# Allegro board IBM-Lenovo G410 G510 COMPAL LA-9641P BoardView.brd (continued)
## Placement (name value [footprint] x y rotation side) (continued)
PC635  -  [C_0402]  167.15 128.39 0 top
PC636  -  [C_0402]  176.52 126.08 270 top
PC637  -  [C_0402]  199.32 11.66 0 top
PC638  -  [C_0402]  170.43 131.14 270 top
PC701  -  [C_0402]  99.53 33.63 180 top
PC702  -  [C_0402]  101.62 28.75 0 top
PC703  -  [C_0402]  104.3 28.78 180 top
PC704  -  [C_0402]  105.73 27.89 90 top
PC705  -  [C_0402]  107.8 29.68 180 top
PC706  -  [C_0402]  107.8 30.83 180 top
PC707  -  [C_0603]  102.15 37.23 270 top
PC708  -  [C_0603]  104.83 35.76 90 top
PC709  -  [C_0603]  116.18 45.19 0 top
PC711  -  [C_0402]  118.59 31.35 0 top
PC712  -  [C_0805]  118.45 29.96 0 top
PC713  -  [C_0805]  118.1 33.61 0 top
PC714  -  [C_MP6VLPS220MC4R2]  113.03 49.15 0 bottom
PC715  -  [C_0402]  118.59 32.3 0 top
PC801  -  [C_0402]  178.47 142.44 90 bottom
PC802  -  [C_0402]  179.36 142.44 90 bottom
PC803  -  [C_0805]  173.42 141.21 180 top
PC804  -  [C_0805]  173.39 139.43 180 top
PC805  -  [C_0402]  186.87 136.34 270 bottom
PC806  -  [C_0603]  180.67 137.09 0 top
PC807  -  [C_D2]  160.89 144.4 90 top
PC808  -  [C_D2]  165.84 144.45 90 top
PC809  -  [C_D2]  160.78 140.14 270 top
PC810  -  [C_D2]  165.72 140 270 top
PC811  -  [C_0402]  169.57 134.43 0 top
PC812  -  [C_0603]  184.25 138.68 0 bottom
PC824  -  [C_0402]  141.99 142.15 270 top
PC825  -  [C_0402]  133.84 138.14 270 top
PC826  -  [C_0402]  132.96 147.23 180 top
PC827  -  [C_0402]  139.89 140.14 270 top
PC828  -  [C_0402]  133.84 144.69 90 top
PC829  -  [C_0402]  137.87 142.62 270 top
PC830  -  [C_0402]  135.81 138.11 270 top
PC831  -  [C_0402]  136.86 146.97 270 top
PC832  -  [C_0402]  137.85 144.69 90 top
PC833  -  [C_0402]  141.87 143.89 90 top
PC834  -  [C_0402]  137.89 140.14 270 top
PC835  -  [C_0402]  135.78 140.14 270 top
PC836  -  [C_0402]  133.84 142.62 270 top
PC837  -  [C_0402]  131.77 144.73 90 top
PC838  -  [C_0402]  131.8 140.14 270 top
PC839  -  [C_0402]  133.84 140.14 270 top
PC840  -  [C_0603]  152.64 138.1 270 top
PC841  -  [C_0603]  153.91 138.08 270 top
PC842  -  [C_0603]  156.45 138.13 270 top
PC843  -  [C_0603]  155.18 138.12 270 top
PC844  -  [C_0603]  143.1 142.34 270 top
PC845  -  [C_0603]  154.62 138.17 270 bottom
PC846  -  [C_0603]  155.87 138.19 270 bottom
PC847  -  [C_0402]  192.46 142.35 180 bottom
PC848  -  [C_0402]  192.67 138.93 0 top
PC849  -  [C_0402]  187.96 144.17 90 bottom
PC850  -  [C_0402]  191.55 140.51 0 bottom
PC851  -  [C_0402]  135.78 142.62 270 top
PC852  -  [C_0402]  138.87 147.04 270 top
PC853  -  [C_0402]  139.86 144.19 90 top
PC854  -  [C_0402]  137.89 138.08 270 top
PC855  -  [C_0402]  139.89 142.62 270 top
PC856  -  [C_0402]  131.8 142.62 270 top
PC857  -  [C_0402]  135.78 144.75 90 top
PC858  -  [C_0603]  182.36 142.78 270 top
PC859  -  [C_0402]  189.9 139.34 180 bottom
PC860  -  [C_0603]  183.3 145.32 270 top
PC861  -  [C_0603]  182.02 145.32 270 top
PC862  -  [C_0402]  189.22 140.22 90 bottom
PC863  -  [C_0402]  189.15 143.29 180 bottom
PC864  -  [C_0402]  185.87 143.96 270 bottom
PC865  -  [C_0402]  171.36 149.27 0 top
PC866  -  [C_0402]  184.95 141.26 270 bottom
PC871  -  [C_0402]  191.77 138.95 90 top
PC872  -  [C_0603]  184.25 137.42 0 bottom
PC873  -  [C_0402]  191.73 137.92 90 bottom
PC874  -  [C_0402]  190.09 144.04 180 top
PC875  -  [C_0402]  191.55 141.4 0 bottom
PC876  -  [C_0603]  187.26 141.21 270 bottom
PC877  -  [C_0603]  186.03 141.2 270 bottom
PC878  -  [C_0402]  176.53 142.45 90 bottom
PC879  -  [C_0402]  177.5 142.43 90 bottom
PC880  -  [C_0805]  178.49 145.24 180 top
PC881  -  [C_0805]  178.49 147.04 180 top
PC901  -  [C_0402]  20.41 117.39 270 top
PC902  -  [C_0402]  17.65 123.01 270 top
PC903  -  [C_0402]  17.67 123.03 0 bottom
PC904  -  [C_0402]  18.59 121.19 270 top
PC905  -  [C_0402]  18.56 119.4 180 bottom
PC906  -  [C_0402]  17.67 121.23 0 bottom
PC907  -  [C_0603]  21.82 122.04 180 top
PC908  -  [C_0402]  18.56 118.49 180 bottom
PC909  -  [C_0402]  21.28 123.13 90 top
PC910  -  [C_0402]  21.34 117.38 270 top
PC911  -  [C_0402]  23.29 118.29 90 top
PC912  -  [C_0402]  25.17 123.13 90 top
PC913  -  [C_0402]  26.48 117.96 90 top
PC914  -  [C_0603]  26.3 119.98 90 top
PC915  -  [C_0402]  29.19 123.42 270 bottom
PC916  -  [C_0402]  20.42 115.48 270 top
PC917  -  [C_0402]  23.22 115.46 270 top
PC918  -  [C_0402]  26.7 115.43 270 top
PC919  -  [C_0603]  27.48 91.24 180 top
PC920  -  [C_0805]  32.41 126.21 180 top
PC922  -  [C_0603]  29.33 116.76 180 bottom
PC923  -  [C_0402]  31.67 94.14 0 top
PC925  -  [C_0805]  32.47 128.02 180 top
PC930  -  [C_0603]  37.24 96.56 180 bottom
PC932  -  [C_0805]  28.41 97.35 0 top
PC933  -  [C_0805]  28.38 99.1 0 top
PC938  -  [C_0805]  26.14 96.91 180 top
PC939  -  [C_0805]  26.13 98.74 180 top
PC940  -  [C_0603]  17.56 96.63 0 top
PC942  -  [C_0402]  25.5 95.49 180 top
PC943  -  [C_0402]  29.31 128.56 270 top
PC944  -  [C_0402]  28.42 128.55 270 top
PC945  -  [C_0402]  25.51 94.59 180 top
PC946  -  [C_0805]  67.54 94.32 90 bottom
PC947  -  [C_0805]  57.69 125.93 90 bottom
PC949  -  [C_0805]  77.23 99.85 270 bottom
PC950  -  [C_0805]  57.69 125.94 90 top
PC951  -  [C_D2]  53.58 123.02 90 top
PC952  -  [C_0805]  70.07 94.32 90 bottom
PC953  -  [C_0805]  59.12 117.23 180 top
PC954  -  [C_D2]  66.36 102.08 0 top
PC955  -  [C_0805]  72.56 99.86 270 bottom
PC956  -  [C_0805]  61.18 125.95 90 bottom
PC957  -  [C_D2]  49.66 122.99 90 bottom
PC958  -  [C_0805]  74.99 99.86 270 bottom
PC959  -  [C_0805]  74.99 98.15 270 top
PC960  -  [C_D2]  54.42 123.02 90 bottom
PC961  -  [C_0805]  72.51 94.31 90 bottom
PC962  -  [C_0805]  65.32 98.15 270 top
PC963  -  [C_0805]  77.24 94.31 90 bottom
PC964  -  [C_0805]  65.29 94.32 90 bottom
PC965  -  [C_0805]  65.32 99.85 270 bottom
PC966  -  [C_0805]  61 94.32 90 bottom
PC967  -  [C_0805]  63.17 99.89 270 bottom
PC968  -  [C_0805]  68.93 119.91 0 bottom
PC969  -  [C_0805]  61.17 125.97 90 top
PC970  -  [C_0805]  58.7 99.87 270 bottom
PC971  -  [C_0805]  59.43 125.94 90 bottom
PC972  -  [C_0805]  70.1 98.23 270 top
PC973  -  [C_0805]  60.91 99.89 270 bottom
PC974  -  [C_0805]  59.43 125.96 90 top
PC975  -  [C_0805]  58.87 94.32 90 bottom
PC976  -  [C_0805]  67.6 99.87 270 bottom
PC977  -  [C_0805]  60.92 98.18 270 top
PC978  -  [C_0805]  72.58 98.16 270 top
PC979  -  [C_0805]  70.1 99.94 270 bottom
PC980  -  [C_0805]  75.07 94.31 90 bottom
PC981  -  [C_0805]  63.17 98.19 270 top
PC982  -  [C_0805]  58.72 98.16 270 top
PC983  -  [C_0805]  63.14 94.31 90 bottom
PC984  -  [C_0805]  76.8 98.15 270 top
PC985  -  [C_MVY25VC220MH10E0-J]  79.5 135.24 45 bottom
PC986  -  [C_EEEFZ1E101P]  25.8 94.9 180 bottom
PC987  -  [C_0402]  22.19 124.04 270 top
PC988  -  [C_0402]  28.56 96 0 top
PC989  -  [C_0402]  28.14 113.47 0 top
PD101  -  [RB715F_SOT323-3]  197.71 29.3 180 top
PD104  -  [1N4148WS-7-F_SOD323-2]  186.49 121.54 180 top
PD105  -  [1N4148WS-7-F_SOD323-2]  181.7 112.42 0 top
PD201  -  [1N4148WS-7-F_SOD323-2]  183.5 65.69 90 top
PD203  -  [1N4148WS-7-F_SOD323-2]  174.49 63.61 90 top
PD301  -  [RB751V-40_SOD323-2]  183.43 167.57 90 top
PD302  -  [1SS355_SOD323-2]  163.08 173.57 180 top
PD303  -  [1SS355_SOD323-2]  165.04 173.64 270 top
PD601  -  [RB751V-40_SOD323-2]  114.35 172.87 270 bottom
PF101  -  [F_451012MRL]  193.61 150.05 270 bottom
PF201  -  [F_451012MRL]  177.15 172.3 0 bottom
PH201  -  [R_0402]  67.1 96.4 0 top
PH802  -  [R_0402]  165.23 140.84 180 bottom
PH901  -  [R_0402]  42.27 129.47 270 bottom
PH902  -  [R_0402]  33.52 115.98 180 top
PJ1  -  [JUMP_43X79]  147.85 93.25 0 top
PJ2  -  [JUMP_43X39]  135.45 63.23 0 top
PJ3  -  [JUMP_43X39]  135.45 60.84 0 top
PJ202  -  [JUMP_43X39]  191.54 61.09 270 top
PJ401  -  [JUMP_43X118]  87.61 13.02 90 top
PJ402  -  [JUMP_43X118]  121.36 11.17 0 bottom
PJ503  -  [JUMP_43X39]  36.9 9.61 0 top
PJ504  -  [JUMP_43X118]  61.6 23.16 270 top
PJ505  -  [JUMP_43X118]  56.24 23.17 270 top
PJ506  -  [JUMP_43X79]  32.3 14.52 0 top
PJ602  -  [JUMP_43X118]  196.55 24 0 top
PJ603  -  [JUMP_43X118]  114.84 164.67 90 bottom
PJ605  -  [JUMP_43X79]  110.56 171.25 0 top
PJ606  -  [JUMP_43X118]  156.87 127.47 90 top
PJ701  -  [JUMP_43X118]  112.44 55.51 270 bottom
PL101  -  [L_1812-1806]  189.89 148.08 180 bottom
PL102  -  [L_1812-1806]  191.88 150.59 180 top
PL201  -  [CHENG_SMB3025500YA_2P]  181.8 168.51 180 bottom
PL301  -  [CYNTE_PCMB063T-100MS_2P]  179.94 158.67 90 bottom
PL302  -  [KARSO_KJ1040-3R3M_2P]  170.67 159.62 90 bottom
PL401  -  [TAI-T_HCB2012KF-121T50_2P]  61.45 3.05 90 bottom
PL402  -  [TAI-T_VMPI0703AR-100M-Z01_2P]  71 8.58 0 top
PL403  -  [TAI-T_HCB2012KF-121T50_2P]  92.56 4.2 0 bottom
PL404  -  [TAI-T_VMPI0703AR-100M-Z01_2P]  107.66 9.55 0 bottom
PL501  -  [CYNTE_PCMB104T-1R0MH_2P]  51.15 7.08 180 top
PL502  -  [TAI-T_HCB2012KF-121T50_2P]  56.41 2.29 0 top
PL601  -  [CYNTE_PCMB063T-1R0MS_2P]  204.71 10.06 90 top
PL603  -  [TAI-T_HCB2012KF-121T50_2P]  190.89 6.84 0 bottom
PL604  -  [CYNTE_PHT32251B-1R0MS_2P]  113.53 167.24 0 top
PL605  -  [CYNTE_PCMB063T-1R0MS_2P]  167.07 128.21 180 bottom
PL606  -  [TAI-T_HCB2012KF-121T50_2P]  175.5 130.48 270 top
PL701  -  [CYNTE_PCMB063T-1R0MS_2P]  111.51 37.12 90 bottom
PL702  -  [TAI-T_HCB2012KF-121T50_2P]  113.64 28.71 180 top
PL801  -  [L_1812-1806]  176.85 142.41 270 top
PL802  -  [CYNTE_PDME064T-R36MS1R405_4P]  168.75 135.51 180 bottom
PL803  -  [CYNTE_PDME064T-R36MS1R405_4P]  168.89 147.88 180 bottom
PL901  -  [L_1812-1806]  76.81 135.85 225 top
PL902  -  [TAI-T_VMPI1004AR-R36M-Z03_4P]  31.52 121.71 0 bottom
PL903  -  [TAI-T_VMPI1004AR-R36M-Z03_4P]  38.34 101.36 90 bottom
PL904  -  [TAI-T_VMPI1004AR-R36M-Z03_4P]  17.75 108.06 0 bottom
PQ101  -  [2N7002DW-7-F_SOT363-6]  183.06 115.67 0 top
PQ102  -  [2N7002DW-7-F_SOT363-6]  196.08 79.66 90 top
PQ201  -  [SSM3K7002FU_SC70-3]  178.38 58.85 270 top
PQ202  -  [2N7002DW-7-F_SOT363-6]  181.84 67.06 180 top
PQ205  -  [2N7002W-T-R7_SOT323-3]  183.41 69.83 0 top
PQ206  -  [2N7002W-T-R7_SOT323-3]  184.43 76.79 0 top
PQ207  -  [2N7002W-T-R7_SOT323-3]  190.8 76.88 0 top
PQ208  -  [2N7002W-T-R7_SOT323-3]  187.81 76.82 0 top
PQ209  -  [2N7002W-T-R7_SOT323-3]  178.33 66.75 180 top
PQ301  -  [AO4407A_SO8]  190.29 160.3 180 top
PQ302  -  [AO4407A_SO8]  186.1 160.09 0 bottom
PQ303  -  [DTC115EUA_SC70-3]  183.74 154.82 180 top
PQ304  -  [DTA144EUA_SC70-3]  182.84 153.55 180 bottom
PQ305  -  [DTC115EUA_SC70-3]  179.99 153.52 180 bottom
PQ306  -  [2N7002KW_SOT323-3]  180.82 149.81 270 bottom
PQ307  -  [2N7002DW-7-F_SOT363-6]  183.08 149.85 0 top
PQ308  -  [2N7002W-T-R7_SOT323-3]  194.44 168.1 270 top
PQ309  -  [AO4466L_SO8]  171.97 154.39 0 top
PQ310  -  [AO4466L_SO8]  170.02 161.88 180 top
PQ311  -  [DTC115EUA_SC70-3]  162.42 170.13 0 top
PQ312  -  [AO4407A_SO8]  175.82 162.14 0 top
PQ313  -  [2N7002W-T-R7_SOT323-3]  162.86 165.85 0 bottom
PQ314  -  [2N7002W-T-R7_SOT323-3]  177.21 154.87 0 bottom
PQ501  -  [TPCA8065-H_PPAK56-8-5]  49.13 3.16 90 bottom
PQ502  -  [TPCA8059-H_PPAK56-8-5]  37.77 3.13 90 bottom
PQ701  -  [AO4466L_SO8]  109.67 36.85 270 top
PQ702  -  [AO4466L_SO8]  117.4 38.95 90 top
PQ801  -  [CSD87351Q5D_SON8-7]  177.27 140.13 270 bottom
PQ802  -  [CSD87351Q5D_SON8-7]  177.4 148.26 270 bottom
PQ901  -  [MDU1516URH_POWERDFN56-8-5]  38.61 126.46 270 top
PQ902  -  [MDU1511RH_POWERDFN56-8-5]  30.73 124.33 270 top
PQ903  -  [MDU1516URH_POWERDFN56-8-5]  37.58 101.01 90 top
PQ904  -  [MDU1511RH_POWERDFN56-8-5]  37.07 98.85 270 top
PQ905  -  [MDU1516URH_POWERDFN56-8-5]  30.2 106.14 180 top
PQ906  -  [MDU1511RH_POWERDFN56-8-5]  20.26 100.81 0 top
PR101  -  [R_0603]  195.57 27.29 90 top
PR102  -  [R_0603]  199.78 28.42 270 top
PR103  -  [R_0402]  193.08 80.47 270 top
PR104  -  [R_0402]  182.65 113.77 90 top
PR105  -  [R_0402]  187.18 120.16 180 top
PR106  -  [R_0402]  184.55 113.77 90 top
PR107  -  [R_0402]  187.18 119.24 180 bottom
PR108  -  [R_0402]  189.72 120.81 90 top
PR109  -  [R_0402]  190.59 119.94 180 top
PR110  -  [R_0402]  195.23 82.98 0 top
PR111  -  [R_0402]  196.12 82.03 180 top
PR201  -  [R_0402]  183.08 173.66 0 top
PR202  -  [R_0402]  185.32 62.89 270 top
PR203  -  [R_0402]  190.91 72.88 0 top
PR204  -  [R_0402]  183.09 172.67 0 top
PR205  -  [R_0402]  181.19 62.86 90 top
PR206  -  [R_0402]  185.16 172.07 270 bottom
PR207  -  [R_0402]  184.22 172.05 270 bottom
PR208  -  [R_0402]  175.89 64.53 270 top
PR209  -  [R_0402]  186.11 172.07 0 bottom
PR210  -  [R_0402]  184.39 62.89 270 top
PR211  -  [R_0402]  180.53 68.11 0 top
PR212  -  [R_0402]  187.84 73 90 top
PR213  -  [R_0402]  187.33 62.9 180 top
PR214  -  [R_0402]  182.19 69.02 180 top
PR215  -  [R_0402]  179.15 60.59 180 top
PR216  -  [R_0402]  180.07 61.43 270 top
PR217  -  [R_0402]  191.8 70.89 180 top
PR220  -  [R_0402]  181.44 71.77 270 top
PR225  -  [R_0402]  187.03 80.2 90 top
PR226  -  [R_0402]  182.07 59.86 0 top
PR227  -  [R_0402]  184.51 81.11 270 top
PR228  -  [R_0402]  182.09 61.24 0 top
PR229  -  [R_0402]  189.28 80.2 90 top
PR230  -  [R_0402]  186 80.2 90 top
PR232  -  [R_0402]  192.07 80.2 90 top
PR233  -  [R_0402]  183.48 80.2 90 top
PR301  -  [R_1206_4P-D]  184.42 159.48 180 top
PR302  -  [R_0402]  183.45 152.29 180 bottom
PR303  -  [R_0402]  181.58 153.05 270 bottom
PR304  -  [R_0402]  185.68 152.64 180 bottom
PR305  -  [R_0402]  185.31 148.81 180 top
PR306  -  [R_0402]  182.34 150.48 270 bottom
PR307  -  [R_0402]  194.94 165.33 90 bottom
PR308  -  [R_0402]  194.02 166.26 270 top
PR309  -  [R_0402]  192.2 165.35 0 top
PR310  -  [R_0402]  194.94 165.33 90 top
PR311  -  [R_0402]  178.19 156.17 180 bottom
PR312  -  [R_0402]  196.78 166.24 270 top
PR314  -  [R_0402]  195.86 166.24 270 top
PR315  -  [R_0402]  192.17 168.09 90 top
PR316  -  [R_0402]  192.17 169.91 0 top
PR317  -  [R_0402]  187.98 170.48 90 top
PR318  -  [R_0402]  187.09 170.48 90 top
PR319  -  [R_1206]  184.47 164.59 270 bottom
PR320  -  [R_0603]  182.74 165.75 270 top
PR321  -  [R_0402]  161.96 168.79 0 top
PR322  -  [R_0402]  162.88 167.86 180 top
PR323  -  [R_1206]  171.65 154.58 180 bottom
PR324  -  [R_1206_4P-D]  170.15 165.72 90 top
PR325  -  [R_0402]  162.88 166.93 180 top
PR326  -  [R0603_0OHM]  183.97 165.97 270 top
PR402  -  [R_0402]  110.06 3.24 0 top
PR403  -  [R_0402]  110.98 4.26 90 top
PR404  -  [R_1206]  72.66 13.05 180 top
PR406  -  [R_1206]  104.41 5.89 180 top
PR407  -  [R_0402]  104.55 9.91 90 top
PR408  -  [R_0402]  103.58 9.92 90 top
PR409  -  [R_0402]  103.58 9.04 0 top
PR410  -  [R_0402]  68.18 3.67 90 bottom
PR411  -  [R_0402]  67.36 7.5 270 bottom
PR412  -  [R_0402]  101.79 9.23 90 top
PR413  -  [R_0402]  102.66 9.23 90 top
PR414  -  [R_0402]  65.58 7.46 270 bottom
PR415  -  [R_0402]  68.24 7.5 270 bottom
PR421  -  [R0603_0OHM]  65.18 4.3 0 top
PR422  -  [R0603_0OHM]  97.62 6.77 90 top
PR501  -  [R_0603]  36.66 7.85 0 top
PR502  -  [R_0402]  28.32 9.81 270 top
PR505  -  [R_0402]  28.35 7.07 90 top
PR506  -  [R_0402]  30.49 12.06 90 top
PR507  -  [R_0402]  31.39 11.21 180 top
PR509  -  [R_0402]  28.39 5.69 0 top
PR511  -  [R_0402]  29.31 4.56 180 top
PR514  -  [R_0603]  31.85 4.37 180 top
PR515  -  [R_1206]  45.08 7.03 270 bottom
PR601  -  [R_0402]  199.59 14.17 270 top
PR602  -  [R_0402]  198.7 13.24 90 bottom
PR603  -  [R_1206]  201.04 9.63 0 bottom
PR604  -  [R_0402]  198.66 14.16 270 top
PR605  -  [R_0402]  197.74 13.26 90 top
PR607  -  [R_0402]  196.75 14.14 0 bottom
PR608  -  [R_0402]  197.67 15.05 180 bottom
PR609  -  [R_0402]  173.11 131.5 90 top
PR610  -  [R_1206]  168.82 124.51 0 bottom
PR611  -  [R_0402]  167.15 129.35 0 top
PR612  -  [R_0402]  170.25 131.99 0 top
PR613  -  [R_0402]  199.6 14.16 270 bottom
PR614  -  [R_1206]  111.14 168.5 270 top
PR615  -  [R_0402]  168.68 130.22 90 top
PR616  -  [R_0402]  169.55 131.14 270 top
PR618  -  [R_0402]  172.17 132.41 270 top
PR623  -  [R_0402]  114.49 171.11 0 top
PR624  -  [R_0402]  114.77 174.8 270 top
PR625  -  [R_0402]  114.74 172 90 top
PR626  -  [R_0402]  115.68 171.99 90 top
PR701  -  [R_0402]  98.61 31.71 0 top
PR702  -  [R_0402]  98.68 29.89 90 top
PR704  -  [R_0402]  102.53 27.83 180 top
PR705  -  [R_0402]  104.31 27.83 180 top
PR706  -  [R_0402]  98.61 32.68 0 top
PR707  -  [R_0402]  107.8 27.68 180 top
PR709  -  [R_0402]  106.89 28.76 0 top
PR711  -  [R_0402]  106.41 32.79 0 top
PR712  -  [R_0402]  99.66 30.83 270 top
PR713  -  [R_0603]  100.92 35.84 90 top
PR714  -  [R_1206]  112.26 44.87 0 top
PR801  -  [R_0402]  186.45 134.19 270 bottom
PR802  -  [R_0402]  187.79 133.7 270 bottom
PR803  -  [R_0402]  185.56 134.19 270 bottom
PR804  -  [R_0402]  183.9 134.19 270 bottom
PR805  -  [R_0402]  183 134.19 270 bottom
PR806  -  [R_0402]  181.57 134.18 270 bottom
PR807  -  [R_0402]  187.77 133.67 270 top
PR808  -  [R_0402]  186.46 133.65 270 top
PR809  -  [R_0402]  185.57 133.66 270 top
PR810  -  [R_0402]  183.9 134.19 270 top
PR811  -  [R_0402]  183 134.19 270 top
PR812  -  [R_0402]  181.57 134.2 270 top
PR813  -  [R_0402]  188.68 132.77 90 top
PR814  -  [R_0402]  185.96 135.43 90 bottom
PR816  -  [R_0402]  190.65 133.73 180 top
PR817  -  [R_0603]  180.67 135.87 0 top
PR818  -  [R_0402]  190.82 134.8 180 bottom
PR819  -  [R_0402]  187.8 136.33 270 bottom
PR820  -  [R_0402]  188.73 132.8 90 bottom
PR826  -  [R_1206]  169.53 138.35 270 top
PR827  -  [R_0402]  182.52 142.6 0 bottom
PR828  -  [R_0402]  182.51 143.53 0 bottom
PR829  -  [R_0402]  182.54 144.45 0 bottom
PR830  -  [R_0402]  191.54 133.74 90 top
PR831  -  [R_0402]  190.82 133 90 bottom
PR832  -  [R_0402]  189.88 133 90 bottom
PR833  -  [R_0402]  192.49 136.68 180 top
PR834  -  [R_0402]  192.51 137.58 180 top
PR835  -  [R_0402]  188.96 136.69 0 bottom
PR836  -  [R_0402]  189.96 135.8 180 bottom
PR840  -  [R_0402]  189.88 137.57 180 bottom
PR841  -  [R_0402]  192.65 137.91 90 bottom
PR842  -  [R_0402]  190.06 143.3 0 bottom
PR843  -  [R_0402]  190.09 143.14 180 top
PR844  -  [R_0402]  185.86 143.18 90 top
PR845  -  [R_0402]  181.4 140.65 180 bottom
PR846  -  [R_0402]  193.58 139.85 180 top
PR847  -  [R_0402]  187.05 145.08 270 bottom
PR848  -  [R_0402]  180.48 139.74 0 bottom
PR849  -  [R_0402]  189.87 138.46 180 bottom
PR850  -  [R_0402]  190.62 145.08 270 bottom
PR851  -  [R_0402]  187.36 143.3 90 top
PR852  -  [R_0603]  183.55 142.77 0 top
PR853  -  [R_0402]  183.43 141.65 180 bottom
PR854  -  [R_0402]  189.34 145.08 270 bottom
PR855  -  [R_1206]  169.78 146.27 90 top
PR856  -  [R_0402]  182.52 146.85 0 bottom
PR857  -  [R_0402]  182.5 147.77 0 bottom
PR858  -  [R_0402]  182.53 145.38 0 bottom
PR859  -  [R_0402]  184.42 145.18 270 top
PR860  -  [R_0402]  188.26 144.22 270 top
PR861  -  [R_0402]  188.34 140.23 90 bottom
PR862  -  [R_0402]  185.85 142.16 180 bottom
PR863  -  [R_0402]  192.83 141.7 90 top
PR864  -  [R_0402]  191.82 140.75 90 top
PR901  -  [R_0402]  19.49 117.39 180 top
PR902  -  [R_0402]  18.58 123.91 180 top
PR903  -  [R_0402]  18.58 123.01 270 top
PR904  -  [R_0402]  17.67 121.19 270 top
PR905  -  [R_0402]  20.31 125.97 0 bottom
PR906  -  [R_0402]  22.15 125.96 90 bottom
PR907  -  [R_0402]  18.56 120.31 180 bottom
PR908  -  [R_0603]  18.2 125.86 270 bottom
PR909  -  [R_0402]  17.67 122.12 0 bottom
PR910  -  [R_0402]  23.49 125.96 90 bottom
PR911  -  [R_0402]  18.58 116.46 0 top
PR912  -  [R_0402]  17.65 117.6 0 bottom
PR913  -  [R_0402]  18.51 116.68 270 bottom
PR914  -  [R0402_0OHM]  19.38 126.83 270 bottom
PR915  -  [R0402_0OHM]  22.17 125.89 270 top
PR916  -  [R_0402]  24.4 125.96 90 bottom
PR917  -  [R_0402]  24.29 123.11 90 top
PR918  -  [R_0603]  20.87 115.52 270 bottom
PR919  -  [R_0603]  23.76 115.51 270 bottom
PR920  -  [R_0603]  26.13 115.51 270 bottom
PR921  -  [R_0402]  26.08 124.03 270 top
PR922  -  [R_0402]  25.93 116.7 0 bottom
PR923  -  [R_0402]  23.54 126.5 0 top
PR924  -  [R_0603]  27.89 116.86 180 top
PR925  -  [R_0603]  27.8 124.51 0 bottom
PR926  -  [R_0402]  21.33 114.56 90 top
PR927  -  [R_0402]  24.14 114.55 90 top
PR928  -  [R_0402]  25.78 114.52 90 top
PR929  -  [R_0402]  20.41 113.71 0 top
PR930  -  [R_0402]  23.23 113.64 0 top
PR931  -  [R_0402]  25.77 112.72 90 top
PR932  -  [R_0402]  23.22 116.58 0 bottom
PR933  -  [R_0402]  27.35 90.17 180 top
PR935  -  [R_0402]  27.48 92.41 180 top
PR936  -  [R_0603]  29.18 93.99 0 top
PR937  -  [R_1206]  30.91 118.09 270 bottom
PR939  -  [R_0402]  26.71 113.64 270 top
PR940  -  [R_1206]  41.2 96.72 180 bottom
PR941  -  [R_0402]  24.13 112.69 180 top
PR942  -  [R_0402]  25.33 125.96 90 bottom
PR943  -  [R_1206]  18.17 100.63 270 top
PR944  -  [R_0402]  21.97 114.97 270 bottom
PR945  -  [R_0402]  26.45 128.5 0 top
PR946  -  [R_0402]  14.55 128.51 0 top
PR947  -  [R_0402]  24.26 91.39 270 top
PR948  -  [R_0402]  18.69 111.25 90 top
PU101  -  [LM393DG_SO8]  185.91 112 0 top
PU201  -  [LM393DG_SO8]  185.67 66.09 0 top
PU202  -  [G9191-330T1U_SOT23-5]  113.76 13.89 180 bottom
PU301  -  [BQ24737RGRR_VQFN20_3P5X3P5]  187.11 165.01 0 top
PU401  -  [SY8208BQNC_QFN10_3X3]  67.1 6.78 180 top
PU402  -  [SY8208CQNC_QFN10_3X3]  102.55 6.7 180 bottom
PU501  -  [RT8207MZQW_WQFN20_3X3]  33.55 9.49 180 top
PU601  -  [SY8208DQNC_QFN10_3X3]  199.06 11.62 180 bottom
PU603  -  [SY8032ABC_SOT23-6]  112.8 170.42 180 bottom
PU604  -  [SY8208DQNC_QFN10_3X3]  170.88 128.79 0 top
PU701  -  [TPS51219RTER_QFN16_3X3]  102.65 30.98 0 top
PU801  -  [ISL62883CHRTZ-T_TQFN40_5X5]  189.7 136.46 90 top
PU901  -  [NCP81103MNTWG_QFN36_5X5]  21.89 123.8 0 bottom
PU902  -  [NCP81151MNTBG_DFN8_2X2]  29.02 92.95 270 top
Q1  -  [2N7002H_SOT23-3]  88.74 88.29 270 top
Q6  -  [DTC124EKAT146_SC59-3]  89.79 102.25 270 top
Q11  -  [2N7002DW-T-R7_SOT363-6]  139.52 75.68 0 bottom
Q37  -  [2N7002H_SOT23-3]  163.59 70.49 180 top
Q63  -  [2N7002DW-T-R7_SOT363-6]  19.36 70.19 180 bottom
Q83  -  [PMV65XP_SOT23-3]  100.14 141.84 0 bottom
Q93  -  [2N7002H_SOT23-3]  22.4 61.9 270 top
Q95  -  [2N7002H_SOT23-3]  17.39 56.56 270 top
Q99  -  [PMV65XP_SOT23-3]  196.2 56.13 0 bottom
Q100  -  [DTC124EKAT146_SC59-3]  192.71 58.34 180 bottom
Q107  -  [2N7002_SOT23-3]  141.53 5.71 0 bottom
Q108  -  [2N7002_SOT23-3]  69.26 17.43 180 top
Q110  -  [2N7002_SOT23-3]  136.05 4.33 90 bottom
Q111  -  [2N7002_SOT23-3]  74.73 16.02 90 top
Q113  -  [2N7002_SOT23-3]  192.35 15.49 0 bottom
Q116  -  [2N7002_SOT23-3]  111.64 53.12 180 top
Q117  -  [DTC124EKAT146_SC59-3]  157.31 70.51 180 top
Q118  -  [2N7002_SOT23-3]  148.64 85.67 180 top
Q120  -  [2N7002_SOT23-3]  152.76 85.73 180 top
Q121  -  [AP2301GN-HF_SOT23-3]  146.94 89.19 270 top
Q124  -  [DTC124EKAT146_SC59-3]  149.7 80.3 270 top
Q130  -  [2N7002DW-T-R7_SOT363-6]  143.33 94.84 0 top
Q156  -  [PMV65XP_SOT23-3]  200.9 141.48 0 top
QL1  -  [PMV65XP_SOT23-3]  41.49 21.47 180 top
QV1  -  [2N7002_SOT23-3]  127.16 106.68 0 top
QV2  -  [2N7002_SOT23-3]  133.59 106.16 90 top
QV3  -  [2N7002DW-T-R7_SOT363-6]  149.44 125.3 0 top
QV6  -  [2N7002_SOT23-3]  155.48 122.56 0 top
QV7  -  [2N7002_SOT23-3]  158.08 117.76 0 top
QV8  -  [AP2301GN-HF_SOT23-3]  150.26 118.49 0 top
QV9  -  [2N7002_SOT23-3]  159.54 122.54 0 top
R1  -  [R_0402]  77.22 100.73 270 top
R5  -  [R_0402]  50.34 74.19 270 top
R6  -  [R_0402]  48.48 74.2 270 top
R7  -  [R_0402]  49.39 74.2 270 top
R8  -  [R_0402]  44.58 110.92 0 top
R9  -  [R_0402]  46.38 110.92 0 top
R10  -  [R0402_0OHM]  46.28 104.49 0 top
R11  -  [R_0402]  46.34 108.15 0 top
R15  -  [R_0402]  45.49 100.67 180 top
R26  -  [R_0402]  88.84 105.83 180 top
R27  -  [R_0402]  88.84 107.18 180 top
R28  -  [R_0402]  94.32 89.94 90 top
R29  -  [R_0402]  89.75 90.72 180 top
R30  -  [R_0402]  87.9 92.49 270 top
R31  -  [R_0402]  10.59 120.44 270 top
R32  -  [R_0402]  95.24 89.93 90 top
R33  -  [R_0402]  11.52 120.44 270 top
R34  -  [R_0402]  154.46 78.56 90 top
R35  -  [R_0402]  87.91 90.69 270 top
R36  -  [R_0402]  88.82 91.6 90 top
R37  -  [R0402_0OHM]  46.3 103.1 0 top
R38  -  [R_0402]  155.37 78.56 90 top
R39  -  [R0402_0OHM]  101.37 150.99 180 top
R40  -  [R_0402]  75.86 35.4 90 top
R41  -  [R_0402]  196.79 139.33 90 bottom
R44  -  [R_0402]  75.86 37.21 0 top
R45  -  [R_0402]  74.86 35.36 270 top
R46  -  [R_0402]  46.4 75.08 180 bottom
R47  -  [R_0402]  73.95 37.2 0 top
R48  -  [R_0402]  31.67 57.81 0 top
R49  -  [R_0402]  32.73 45.07 0 top
R54  -  [R_0402]  31.73 56.9 270 top
R59  -  [R_0402]  32.75 44.16 0 top
R60  -  [R_0402]  76.32 101.6 0 top
R62  -  [R_0402]  46.42 94.56 180 bottom
R63  -  [R_0402]  46.43 98.19 180 bottom
R64  -  [R_0402]  74.93 117.37 180 top
R66  -  [R_0402]  77.24 102.48 90 top
R67  -  [R_0402]  46.41 95.5 180 bottom
R68  -  [R_0402]  47.22 102.08 180 top
R78  -  [R_0603]  88.83 99.62 0 top
R79  -  [R_0402]  54.51 118.68 0 top
R81  -  [R_0402]  54.53 117.71 180 top
R83  -  [R_0402]  51.74 117.67 270 top
R84  -  [R_0402]  56.34 118.66 0 top
R87  -  [R_0402]  53.61 116.81 0 top
R88  -  [R_0402]  88.88 110.29 90 top
R89  -  [R_0402]  87.95 111.21 270 top
R93  -  [R_0402]  95.87 43.7 0 top
R94  -  [R_0402]  140.11 90.79 0 bottom
R95  -  [R_0402]  138.63 96.36 90 top
R96  -  [R_0402]  139.47 91.65 180 top
R97  -  [R_0402]  135.63 91 180 bottom
R98  -  [R_0402]  140.4 94.22 0 top
R99  -  [R_0402]  139.2 90.76 180 bottom
R100  -  [R_0402]  139 84.12 270 top
R101  -  [R_0402]  139.87 85.01 180 top
R102  -  [R_0402]  120.95 94.22 270 bottom
R104  -  [R_0402]  140.01 84.02 180 bottom
R105  -  [R_0402]  140.57 82.23 90 bottom
R106  -  [R_0402]  137.64 83.97 90 bottom
R107  -  [R_0402]  118.21 91.37 180 bottom
R108  -  [R_0402]  120.05 94.24 270 bottom
R110  -  [R_0402]  127.39 98.29 270 top
R119  -  [R_0402]  125.34 98.31 270 bottom
R121  -  [R_0402]  124.47 98.3 270 bottom
R122  -  [R_0402]  125.34 97.39 90 top
R123  -  [R_0402]  124.35 100.54 270 top
R124  -  [R_0402]  124.35 97.39 90 top
R125  -  [R_0402]  131.5 71.36 90 top
R126  -  [R_0402]  132.59 71.35 90 top
R132  -  [R_0402]  127.1 75.23 90 bottom
R133  -  [R0402_0OHM]  89.73 91.59 90 top
R134  -  [R_0402]  138.56 93.4 270 top
R135  -  [R_0402]  116.72 88.24 0 bottom
R136  -  [R_0402]  134.17 94.68 180 bottom
R138  -  [R_0402]  121.41 100.5 270 top
R139  -  [R0402_0OHM]  134.42 97.85 180 top
R143  -  [R_0402]  139.46 92.49 90 top
R145  -  [R_0402]  119.31 73.88 0 bottom
R148  -  [R_0402]  134.17 93.77 180 bottom
R149  -  [R_0402]  134.4 98.75 90 top
R156  -  [R_0402]  133.93 100.2 90 bottom
R157  -  [R_0402]  121.42 96.58 180 bottom
R158  -  [R_0402]  121.85 93.32 90 bottom
R167  -  [R_0402]  139.94 89.49 180 top
R168  -  [R_0402]  135.64 90.12 180 bottom
R169  -  [R_0402]  132.31 93.57 90 bottom
R172  -  [R_0402]  119.13 94.25 270 bottom
R173  -  [R_0402]  142.57 86.88 180 top
R176  -  [R_0402]  123.41 102.59 270 top
R177  -  [R_0402]  126.39 94.11 270 bottom
R178  -  [R_0402]  124.18 93.38 90 bottom
R181  -  [R_0402]  126.27 99.15 90 top
R182  -  [R_0402]  124.33 102.6 270 top
R183  -  [R_0402]  116.45 83.52 0 bottom
R184  -  [R_0402]  123.41 99.17 90 top
R185  -  [R0402_0OHM]  124.85 69.61 90 top
R186  -  [R0402_0OHM]  122.32 72.29 270 top
R187  -  [R0402_0OHM]  123.97 69.61 90 top
R188  -  [R0402_0OHM]  123.26 72.29 270 top
R189  -  [R0402_0OHM]  125.29 71.41 90 top
R191  -  [R_0402]  130.05 98.81 180 bottom
R192  -  [R_0402]  116.44 82.63 0 bottom
R193  -  [R_0402]  112.49 83.41 0 top
R194  -  [R_0402]  112.48 84.31 0 top
R195  -  [R_0402]  125.09 93.37 90 bottom
R197  -  [R_0402]  134.71 78.36 180 bottom
R199  -  [R_0402]  134.7 79.26 180 bottom
R201  -  [R_0402]  129.15 97.88 0 bottom
R202  -  [R_0402]  112.29 94.93 270 top
R203  -  [R_0402]  113.2 94.94 270 top
R205  -  [R_0402]  133.98 71.38 90 top
R209  -  [R_0402]  136.16 75.6 180 bottom
R211  -  [R_0402]  134.93 71.37 90 top
R214  -  [R_0402]  122.39 76.2 0 bottom
R215  -  [R_0402]  120.49 72.21 180 top
R216  -  [R_0402]  136.31 98.27 270 top
R221  -  [R_0402]  130.03 94.14 270 bottom
R222  -  [R_0402]  137.18 98.28 270 top
R223  -  [R_0402]  120.68 89.6 180 bottom
R226  -  [R_0402]  128.21 93.22 90 bottom
R227  -  [R_0402]  129.13 93.22 90 bottom
R228  -  [R_0402]  119.52 76.13 0 bottom
R229  -  [R_0402]  108.5 106.52 180 bottom
R230  -  [R_0402]  109.88 106.52 0 bottom
R237  -  [R_0402]  110.46 102.13 270 bottom
R240  -  [R_0402]  109.37 101.22 90 bottom
R242  -  [R_0402]  132.36 82.39 0 bottom
R244  -  [R_0402]  112.49 82.54 0 top
R245  -  [R0402_0OHM]  109.88 105.6 0 bottom
R246  -  [R0402_0OHM]  108.5 105.59 180 bottom
R247  -  [R_0402]  128.17 101.18 270 bottom
R248  -  [R_0402]  141.73 76.96 180 top
R249  -  [R_0402]  140.08 88.1 180 top
R252  -  [R_0402]  131.76 100.27 90 bottom
R253  -  [R_0402]  127.25 100.26 90 bottom
R255  -  [R_0402]  114.28 97.34 90 top
R256  -  [R_0402]  126.33 100.25 90 bottom
R258  -  [R_0402]  116.09 97.35 90 top
R259  -  [R_0402]  140.08 87.22 180 top
R260  -  [R_0402]  125.44 103.19 270 bottom
R261  -  [R_0402]  142.87 85.32 0 bottom
R262  -  [R_0402]  115.18 97.35 90 top
R265  -  [R_0402]  120.52 95.69 0 bottom
R266  -  [R_0402]  136.92 95.85 180 bottom
R267  -  [R_0402]  135.1 95.85 180 bottom
R268  -  [R_0402]  121.41 98.24 270 top
R270  -  [R_0402]  120.16 102.73 0 top
R271  -  [R_0402]  118.17 98.25 270 top
R272  -  [R_0402]  127.3 94.12 270 bottom
R273  -  [R_0402]  129.11 100.25 90 bottom
R274  -  [R_0402]  121.07 102.73 180 bottom
R275  -  [R_0402]  117.92 97.34 90 bottom
R276  -  [R_0402]  140.81 77.92 0 top
R277  -  [R_0402]  133.46 75.64 270 bottom
R278  -  [R_0402]  113.17 97.66 270 top
R279  -  [R_0402]  139.55 78.12 180 top
R280  -  [R_0402]  120.03 97.32 90 top
R281  -  [R_0402]  121.07 101.81 180 top
R282  -  [R_0402]  134.38 74.72 90 bottom
R283  -  [R_0402]  113.17 95.84 180 top
R286  -  [R_0402]  140.81 79.16 0 top
R287  -  [R_0402]  140.83 80.15 0 top
R288  -  [R_0402]  139.54 79.12 180 top
R289  -  [R_0402]  139.53 80.16 180 top
R290  -  [R_0402]  135.31 98.26 270 top
R291  -  [R0603_0OHM]  114.9 87.15 0 bottom
R297  -  [R0805_0OHM]  122.86 66.7 270 top
R299  -  [R0805_0OHM]  138.14 71.97 270 top
R300  -  [R0805_0OHM]  123.16 74.65 0 bottom
R301  -  [R0603_0OHM]  178.82 76.87 0 top
R302  -  [R0805_0OHM]  135.82 82.01 270 bottom
R303  -  [R_0402]  151.45 10.7 270 top
R304  -  [R_0603]  158.14 75.02 180 top
R307  -  [R0402_0OHM]  136.22 87.12 0 bottom
R309  -  [R_0402]  46.38 109.99 0 top
R311  -  [R_0402]  124.34 99.63 90 bottom
R312  -  [R_0402]  133.51 98.75 90 top
R313  -  [R0402_0OHM]  126.18 71.41 90 top
R335  -  [R_0402]  151.12 74.87 180 top
R401  -  [R_0402]  191.74 47.15 180 bottom
R402  -  [R_0402]  191.74 48.09 180 bottom
R403  -  [R_0402]  191.65 50.24 180 bottom
R404  -  [R_0402]  191.65 51.17 180 bottom
R405  -  [R_0402]  199.12 164.56 0 top
R406  -  [R_0402]  159.6 72.35 180 top
R408  -  [R_0402]  92.09 141.17 270 bottom
R411  -  [R_0402]  12.61 122.21 90 bottom
R412  -  [R_0402]  14.59 122.25 90 bottom
R435  -  [R_0402]  101.11 137.08 90 bottom
R438  -  [R_0402]  90.9 127.98 180 bottom
R441  -  [R0402_0OHM]  100.57 148.43 150 top
R458  -  [R_0402]  94.64 102.19 270 top
R485  -  [R_0402]  26.54 62.48 270 top
R488  -  [R_0402]  14.08 65.58 0 top
R501  -  [R_0402]  197.6 135.34 270 bottom
R502  -  [R_0402]  196.65 135.35 270 bottom
R505  -  [R_0402]  199.14 162.68 0 top
R506  -  [R_0402]  199.12 163.63 0 top
R507  -  [R_0402]  199.12 161.72 0 top
R522  -  [R_0402]  166.28 72.32 270 top
R550  -  [R0805_0OHM]  167.3 117.99 180 top
R551  -  [R0805_0OHM]  83.46 121.43 0 top
R552  -  [R0805_0OHM]  156.29 124.83 0 bottom
R553  -  [R0805_0OHM]  92.15 142.25 90 bottom
R555  -  [R_0402]  181.89 56.06 270 top
R568  -  [R_0402]  190.77 52.14 0 bottom
R581  -  [R0603_0OHM]  98.47 165.84 0 bottom
R589  -  [R_0402]  178.8 80.95 0 top
R590  -  [R_0402]  172.26 93.64 270 top
R593  -  [R_0402]  163.41 81.84 0 bottom
R594  -  [R_0402]  158.23 81.36 180 top
R595  -  [R_0402]  169.92 72.32 270 top
R598  -  [R_0402]  158.24 79.55 180 top
R600  -  [R_0402]  164.33 84.46 180 bottom
R601  -  [R_0402]  168.9 77.94 0 bottom
R603  -  [R_0402]  158.24 80.44 180 top
R604  -  [R_0402]  164.33 83.58 180 bottom
R605  -  [R_0402]  179.73 87.04 180 top
R606  -  [R_0402]  178.82 87.99 0 top
R608  -  [R_0402]  178.81 88.96 0 top
R619  -  [R_0402]  182.69 86.38 270 top
R623  -  [R_0402]  149.68 10.69 270 top
R627  -  [R_0402]  181.74 89.95 270 top
R628  -  [R0402_0OHM]  102.52 112.89 90 top
R642  -  [R_0402]  100.55 113.8 270 top
R643  -  [R_0402]  101.53 113.8 270 top
R644  -  [R_0603]  134.88 6.95 0 bottom
R645  -  [R_0603]  70.67 19.34 180 top
R646  -  [R_0402]  133.09 2.96 0 bottom
R647  -  [R_0402]  75.59 17.6 0 top
R649  -  [R_0402]  133.07 3.88 0 bottom
R650  -  [R_0402]  77.39 16.69 90 top
R652  -  [R_0402]  157.77 73.27 180 top
R653  -  [R_0402]  156.86 72.35 0 top
R655  -  [R_0603]  192.97 18.69 270 bottom
R659  -  [R_0603]  113.04 55.12 180 top
R669  -  [R_0402]  170.79 72.32 270 top
R675  -  [R_0402]  194.9 52.13 0 bottom
R683  -  [R0402_0OHM]  199.96 27.49 90 bottom
R684  -  [R0402_0OHM]  94.4 140.08 330 bottom
R687  -  [R0402_0OHM]  200.83 27.49 90 bottom
R688  -  [R0402_0OHM]  94.85 140.84 330 bottom
R689  -  [R0402_0OHM]  138.64 95.53 270 top
R694  -  [R_0402]  163.41 85.37 0 bottom
R695  -  [R_0402]  161.64 85.37 0 bottom
R701  -  [R_0402]  169.08 66.43 180 top
R710  -  [R_0402]  196.93 54.72 90 top
R716  -  [R_0402]  100.23 149.69 330 top
R722  -  [R_0402]  201.1 147.26 0 top
R740  -  [R_0402]  172.59 72.33 270 top
R764  -  [R_0402]  152.35 10.7 270 top
R765  -  [R_0402]  150.57 10.69 270 top
R777  -  [R_0603]  145.85 87.23 270 top
R778  -  [R_0402]  151.84 89.09 270 top
R780  -  [R_0402]  152.64 77.69 180 top
R781  -  [R_0402]  153.56 79.37 90 top
R813  -  [R0805_0OHM]  97.96 151.36 180 bottom
R868  -  [R_0402]  199.51 152.98 270 top
R869  -  [R_0402]  200.39 152.98 270 top
R5581  -  [R_0402]  201.1 146.34 270 top
R5583  -  [R_0402]  199.14 139.63 0 top
RA1  -  [R_0402]  147.8 55.76 270 top
RA2  -  [R_0402]  146.88 55.76 270 top
RA4  -  [R0402_0OHM]  160.13 55.37 270 top
RA5  -  [R_0402]  160.26 43.89 270 top
RA6  -  [R_0402]  163 43.89 270 top
RA7  -  [R_0402]  162.08 43.89 270 top
RA8  -  [R_0402]  161.18 43.89 270 top
RA9  -  [R_0402]  162.87 48.69 180 top
RA12  -  [R_0402]  154.16 44.96 270 top
RA13  -  [R_0402]  147.57 53.43 180 top
RA14  -  [R_0402]  147.54 50.57 0 top
RA15  -  [R_0402]  163.18 52.3 90 top
RA16  -  [R_0402]  153.27 44.96 270 top
RA17  -  [R_0402]  155.05 44.96 270 top
RA18  -  [R_0402]  155.94 44.96 270 top
RA19  -  [R_0402]  146.65 51.48 0 top
RA20  -  [R_0402]  146.65 52.5 0 top
RA21  -  [R_0402]  159.52 58.4 270 top
RA22  -  [R_0402]  161.98 54.28 180 top
RA23  -  [R_0402]  156.82 43.76 270 top
RA492  -  [R_0402]  161.98 53.26 180 top
RC1  -  [R_0402]  88 102.56 270 top
RL3  -  [R_0402]  41.72 17.61 0 top
RL4  -  [R_0402]  38.31 25.6 180 top
RL6  -  [R_0402]  43.92 26.89 180 top
RL7  -  [R0402_0OHM]  42.12 26.01 90 top
RL8  -  [R_0402]  36.61 32.2 90 top
RL9  -  [R_0402]  41.24 26.01 90 top
RL10  -  [R_0402]  39.73 26.88 270 top
RL11  -  [R_0402]  38.32 26.52 180 top
RL12  -  [R_0402]  34.43 22.67 180 top
RL14  -  [R_0805]  16.52 88.77 0 top
RP1  -  [RP_0804_8P4R]  135.72 84.42 90 bottom
RP2  -  [RP_0804_8P4R]  110.65 90.56 0 bottom
RP5  -  [RP_0804_8P4R]  17.52 64.35 0 top
RP6  -  [RP_0804_8P4R]  17.86 61.1 0 top
RP9  -  [RP_0804_8P4R]  126.56 98.87 270 bottom
RP10  -  [RP_0804_8P4R]  131.32 98.8 270 bottom
RP12  -  [RP_0804_8P4R]  138.1 80.78 0 bottom
RP13  -  [RP_1206_10P8R]  138.42 87.97 0 bottom
RP14  -  [RP_1206_10P8R]  130.96 97.69 90 top
RP15  -  [RP_1206_10P8R]  114.74 101.12 0 top
RP16  -  [RP_0804_8P4R]  144.13 75.49 180 bottom
RP17  -  [RP_0804_8P4R]  148.84 97.61 270 top
RP18  -  [RP_0804_8P4R]  32.77 60.38 270 top
RP19  -  [RP_0804_8P4R]  45.74 113.87 0 top
RP21  -  [RP_0804_8P4R]  14.88 73.3 90 top
RP22  -  [RP_0804_8P4R]  13.7 109.14 270 top
RP23  -  [RP_0804_8P4R]  127.42 70.69 90 top
RT1  -  [R0805_0OHM]  88.36 133.17 270 bottom
RT4  -  [R_0402]  84.25 135.11 90 top
RT8  -  [R_0402]  80.48 127.21 0 top
RT9  -  [R_0402]  87 132.69 270 bottom
RT10  -  [R_0402]  86.04 132.69 270 bottom
RT12  -  [R_0402]  85.13 136.03 270 top
RV1  -  [R_0402]  132.59 132.53 90 top
RV2  -  [R_0402]  155.77 154.01 0 bottom
RV3  -  [R_0402]  133.86 132.53 90 top
RV4  -  [R_0402]  131.09 126.24 180 top
RV5  -  [R_0402]  151.03 123.88 0 top
RV6  -  [R_0402]  132.03 123.18 0 top
RV11  -  [R_0402]  138.14 131.06 90 top
RV12  -  [R_0402]  149.83 137.84 90 top
RV13  -  [R_0402]  155.19 144.89 0 bottom
RV14  -  [R_0402]  154.25 144.9 270 bottom
RV16  -  [R0402_0OHM]  151.8 72.06 0 top
RV17  -  [R0402_0OHM]  151.8 72.95 0 top
RV18  -  [R_0402]  131.11 123.48 90 top
RV19  -  [R_0402]  130.28 125.33 0 top
RV20  -  [R_0402]  136.07 124.15 180 top
RV21  -  [R_0402]  152.38 131.93 180 top
RV22  -  [R_0402]  136.93 124.15 0 top
RV23  -  [R_0402]  145.95 124.46 90 top
RV24  -  [R_0402]  150.17 123.88 180 top
RV25  -  [R_0402]  149.89 128.45 0 top
RV26  -  [R_0402]  152.38 130.1 180 top
RV27  -  [R_0402]  135.15 125.17 0 top
RV28  -  [R_0402]  151.47 132.86 0 top
RV29  -  [R_0402]  137.84 125.17 180 top
RV30  -  [R_0402]  146.85 124.41 0 top
RV31  -  [R_0402]  152.37 131.02 180 top
RV32  -  [R_0402]  153.35 131.19 270 bottom
RV33  -  [R_0402]  155.17 149.45 0 bottom
RV34  -  [R_0402]  155.17 150.34 0 bottom
RV35  -  [R_0402]  160.76 117.22 90 top
RV36  -  [R_0603]  155.45 118.4 270 top
RV37  -  [R_0402]  152.88 120.47 90 top
RV38  -  [R_0402]  152.14 122.33 180 top
RV39  -  [R_0603]  129.84 109.71 90 top
RV41  -  [R_0402]  134.41 107.74 0 top
RV42  -  [R_0402]  133.46 108.76 0 top
RV43  -  [R0402_0OHM]  144.89 127.75 90 top
RV44  -  [R_0402]  153.37 126.67 0 bottom
RV47  -  [R_0402]  135.73 134.51 90 top
RV48  -  [R_0402]  146.54 148.2 270 top
RV49  -  [R_0402]  125.97 143.69 0 top
RV50  -  [R_0402]  130.32 139.86 90 top
RV51  -  [R_0402]  156.05 148.39 180 bottom
RV52  -  [R_0402]  156.05 146.69 180 bottom
RV53  -  [R_0402]  147.43 148.21 270 top
RV54  -  [R_0402]  143.94 147.3 180 top
RV55  -  [R_0402]  128.46 143.58 0 top
RV56  -  [R_0402]  130.31 141.66 90 top
RV57  -  [R_0402]  142.98 149.1 270 top
RV58  -  [R_0402]  154.21 148.52 270 bottom
RV59  -  [R_0402]  154.23 146.73 270 bottom
RV60  -  [R_0402]  103.63 136.13 180 top
RV61  -  [R_0402]  103.63 137.06 180 top
RV62  -  [R_0402]  103.63 132.45 90 top
RV63  -  [R_0402]  103.62 128.82 90 bottom
RV64  -  [R_0402]  103.63 134.23 180 top
RV65  -  [R_0402]  103.62 130.66 180 bottom
RV66  -  [R_0402]  103.58 150.92 180 top
RV67  -  [R_0402]  103.55 146.49 90 bottom
RV68  -  [R_0402]  103.57 154.7 270 top
RV69  -  [R_0402]  103.58 150.04 180 top
RV70  -  [R_0402]  103.59 148.25 180 bottom
RV71  -  [R_0402]  103.59 152.84 180 top
RV72  -  [R_0402]  133.32 174.87 90 top
RV73  -  [R_0402]  132.44 174.87 90 top
RV74  -  [R_0402]  127.93 174.89 0 top
RV75  -  [R_0402]  124.19 174.89 0 bottom
RV76  -  [R_0402]  129.73 174.85 90 top
RV77  -  [R_0402]  125.98 174.89 90 bottom
RV78  -  [R_0402]  147.76 175.78 270 top
RV79  -  [R_0402]  146.82 174.86 90 top
RV80  -  [R_0402]  145.89 161.88 180 bottom
RV81  -  [R_0402]  145.87 174.86 90 top
RV82  -  [R_0402]  148.68 174.87 90 top
RV83  -  [R_0402]  147.29 161.87 0 bottom
RV84  -  [R_0402]  103.65 131.56 180 top
RV85  -  [R_0402]  115.68 135.52 90 bottom
RV86  -  [R_0402]  115.6 147.26 270 top
RV87  -  [R_0402]  103.55 150.23 90 bottom
RV88  -  [R_0402]  125.98 174.89 90 top
RV89  -  [R_0402]  131.95 161.82 0 bottom
RV90  -  [R_0402]  147.61 174.9 0 bottom
RV91  -  [R_0402]  142.49 161.85 0 top
SW4  -  [SW_TJG-533-V-T-R_6P]  129.71 15.45 90 top
SW5  -  [SW_TJG-533-V-T-R_6P]  170.76 15.45 90 top
SW6  -  [SW_TJG-533-V-T-R_6P]  114.15 6.65 90 top
SW7  -  [SW_TJG-533-V-T-R_6P]  164.35 6.65 90 top
T1  -  [TPC12]  140.87 132.66 90 top
T2  -  [TPC12]  139.31 132.7 90 top
T3  -  [TPC12]  161.08 44.79 0 top
T4  -  [TPC12]  139.15 124.43 180 bottom
T6  -  [TPC12]  137.79 124.38 180 bottom
T12  -  [TPC12]  63.85 86.11 0 top
T13  -  [TPC12]  59.49 86.96 0 top
T14  -  [TPC12]  71.73 106.99 0 top
T15  -  [TPC12]  48.5 103.45 0 top
T16  -  [TPC12]  44.43 96.04 180 bottom
T17  -  [TPC12]  46.02 96.91 180 bottom
T18  -  [TPC12]  47.48 99.38 0 top
T19  -  [TPC12]  44.5 97.52 180 bottom
T20  -  [TPC12]  129.23 91.64 180 bottom
T21  -  [TPC12]  138.36 90.36 0 top
T22  -  [TPC12]  135.91 94.78 180 bottom
T23  -  [TPC12]  48.39 112.02 0 top
T24  -  [TPC12]  140.5 124.32 180 bottom
T25  -  [TPC12]  143.17 124.45 180 bottom
T26  -  [TPC12]  141.85 124.32 180 bottom
T27  -  [TPC12]  153.08 136.42 180 bottom
T28  -  [TPC12]  153.07 135.02 180 bottom
T31  -  [TPC12]  48.54 113.38 0 top
T66  -  [TPC12]  10.14 116.38 0 top
TL1  -  [BOTH_NS0013LF_16P]  26.11 85.14 270 bottom
TV12  -  [TPC12]  121.9 124.38 180 bottom
TV13  -  [TPC12]  153.3 155.01 270 bottom
TV14  -  [TPC12]  153.3 127.94 270 bottom
TV15  -  [TPC12]  141.02 133.97 0 top
U1  -  [74AHC1G09GW_TSSOP5]  92.9 90.85 90 top
U4  -  [DH82LPMS-QC4C_FCBGA_695P_A39]  135.31 94.13 270 top
U6  -  [NC7SZ08P5X_NL_SC70-5]  120.7 98.69 0 bottom
U8  -  [MX25L1605AM2C-12G_SO8]  108.85 87.62 180 bottom
U9  -  [ADM1032ARMZ-2REEL_MSOP8]  149.34 71.52 90 top
U10  -  [TPD7S019-15DBQR_SSOP16]  14.59 114.86 180 bottom
U31  -  [KB9012QF-A2_LQFP128_14X14]  176.42 76.56 90 top
U35  -  [G547I2P81U_MSOP8]  19.3 28.96 0 top
U36  -  [G547I2P81U_MSOP8]  198.46 107.19 180 bottom
U38  -  [DMN3030LSS-13_SOP8L-8]  130.43 7.36 270 bottom
U39  -  [DMN3030LSS-13_SOP8L-8]  83.56 18.85 180 top
U72  -  [APL3512ABI-TRG_SOT23-5]  90.49 145.12 270 bottom
U73  -  [AP2330W-7_SC59-3]  14.97 67.74 180 top
UA1  -  [CX20751-11Z_QFN40_5X5]  158.93 47.27 90 top
UL1  -  [AR8161-AL3A-R_QFN40_5X5]  34.38 25.26 90 top
UT2  -  [RTD2132S-GR_QFN32_5X5]  83.28 131.98 270 top
UV1  -  [MARS-PRO_FCBGA_962P_A39]  122.45 155.07 270 bottom
UV2  -  [NC7SZ08P5X_NL_SC70-5]  133.13 124.96 90 top
UV4  -  [AO4304L_SO8]  136 113.52 270 top
UV5  -  [MT41J128M16JT-093_FBGA_96P_A39]  112.83 126.05 180 top
UV6  -  [MT41J128M16JT-093_FBGA_96P_A39]  106.43 126.05 0 bottom
UV7  -  [MT41J128M16JT-093_FBGA_96P_A39]  106.38 158.32 0 top
UV8  -  [MT41J128M16JT-093_FBGA_96P_A39]  112.78 158.32 180 bottom
UV9  -  [K4W4G1646B-HC11_FBGA_96P_A39]  122.17 165.17 90 top
UV10  -  [K4W4G1646B-HC11_FBGA_96P_A39]  122.17 171.57 270 bottom
UV11  -  [K4W4G1646B-HC11_FBGA_96P_A39]  155.51 165.17 90 bottom
UV12  -  [K4W4G1646B-HC11_FBGA_96P_A39]  155.51 171.57 270 top
Y1  -  [Y_CM31532768DZFT_2P]  140.27 95.57 90 top
Y2  -  [Y_X3G025000DC1H_4P]  118.49 68.24 0 top
YL1  -  [Y_X3G025000DC1H_4P]  40.14 31.19 270 top
YV1  -  [Y_X3G025000DC1H_4P]  157.23 132.22 270 bottom

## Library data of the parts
C4 C6 C9-C16 C25-C32 C35 C37 C39-C48 C53 C66 C67 C77-C80 C82-C85 C87 C89 C90 C93 C100-C107 C109 C111 C112 C114 C116 C118-C120 C122-C127 C130-C132 C134-C136 C138 C139 C143-C146 C149 C152-C160 C162-C167 C169-C171 C173-C184 C186 C190-C193 C411 C412 C492-C494 C520 C522-C527 C529 C531 C535-C537 C543 C544 C547 C587 C596-C599 C604 C605 C607 C613-C616 C653-C664 C696 C726 C727 C781 C847-C850 C1322 C1331 CA2 CA4 CA5 CA7 CA9-CA11 CA17 CA19-CA21 CA25-CA28 CA31-CA40 CA42-CA46 CA64-CA66 CL1 CL2 CL4 CL5 CL7-CL14 CL17-CL26 CL28 CL29 CL31 CT2 CT3 CT5 CT7 CT8 CT10-CT12 CV1-CV18 CV20 CV21 CV23 CV26-CV29 CV31 CV32 CV34-CV37 CV39-CV42 CV44 CV45 CV52-CV55 CV58 CV59 CV61-CV64 CV71-CV84 CV86 CV87 CV90 CV91 CV94-CV104 CV106-CV109 CV112 CV113 CV117-CV122 CV124-CV127 CV129 CV130 CV132 CV134-CV136 CV141 CV144-CV150 CV152 CV154-CV156 CV158-CV160 CV164-CV173 CV175-CV179 CV181 CV183 CV186-CV198 PC101-PC109 PC201-PC203 PC207-PC210 PC212 PC213 PC301 PC303-PC309 PC311 PC324 PC403 PC404 PC417-PC419 PC431-PC435 PC503 PC506 PC508 PC509 PC513 PC603 PC607 PC617 PC619 PC621 PC625 PC635-PC638 PC701-PC706 PC711 PC715 PC801 PC802 PC805 PC811 PC824-PC839 PC847-PC857 PC859 PC862-PC866 PC871 PC873-PC875 PC878 PC879 PC901-PC906 PC908-PC913 PC915-PC918 PC923 PC942-PC945 PC987-PC989 = C_0402
C54-C58 C65 C68-C76 C86 C88 C91 C92 C94-C99 C108 C110 C113 C115 C128 C129 C133 C140 C147 C172 C185 C516 C519 C548 C591 C602 C608 C667 C720-C725 C780 C782 C783 CA1 CA3 CA6 CA8 CA15 CA16 CA18 CA22-CA24 CA29 CA30 CA41 CL3 CL6 CL15 CL16 CL30 CL61-CL64 CT1 CT4 CT6 CT9 CV19 CV22 CV30 CV33 CV38 CV43 CV46 CV48 CV49 CV56 CV57 CV60 CV65 CV67-CV70 CV85 CV88 CV89 CV92 CV105 CV115 CV116 CV128 CV138 CV139 CV161 CV162 CV174 CV184 CV185 PC211 PC302 PC312 PC314 PC317 PC320 PC402 PC407 PC414 PC415 PC421 PC422 PC429 PC430 PC510-PC512 PC517 PC601 PC602 PC605 PC606 PC613 PC628 PC630 PC632 PC634 PC707-PC709 PC806 PC812 PC840-PC846 PC858 PC860 PC861 PC872 PC876 PC877 PC907 PC914 PC919 PC922 PC930 PC940 = C_0603
C59 = C_MP2VLPS330MC4R2
C60-C64 C137 C541 PC310 PC313 PC315 PC316 PC318 PC319 PC322 PC323 PC405 PC406 PC408-PC413 PC416 PC420 PC423-PC428 PC501 PC504 PC505 PC520 PC604 PC608-PC612 PC618 PC620 PC622 PC626 PC627 PC629 PC631 PC633 PC712 PC713 PC803 PC804 PC880 PC881 PC920 PC925 PC932 PC933 PC938 PC939 PC946 PC947 PC949 PC950 PC952 PC953 PC955 PC956 PC958 PC959 PC961-PC984 = C_0805
C81 = C_6SVPE220MX
C714 C736 = C_MP6VL220MC6
CLRP2 CLRP3 J11 J12 = SHORTPADS: User Part Number: PART#
CV66 = C_B2
D1 DV1 = CH751H-40PT_SOD323-2
D15 D24 = PSOT24C_SOT23-3
D22 D31 DA3 DL1 = AZC099-04SPR7G_SOT23-6
D25 = PJDLC05_SOT23-3
D26 = DAN202UT106_SC70-3
D27-D30 D32 = YSCLAMP0524P_SLP2510P8-10-9
DA1 DA2 = AZ5125-02SPR7G_SOT23-3
DLL1 = BS4200N-C-LV_SMB-F2
FD1-FD4 = FIDUCIAL_C40M80
H1-H3 = H_3P8
H4 H5 = H_3P3
H7 H8 H10-H12 H18 = H_2P8
H16 = H_2P5X3P5N
H17 = H_3P0N
J1 PJ401 PJ402 PJ504 PJ505 PJ602 PJ603 PJ606 PJ701 = JUMP_43X118
J6 J9 J10 PJ1 PJ506 PJ605 = JUMP_43X79
JBATT1 JBATT2 = SUYIN_200082GR007M229ZR_7P-T
JCPU1 = INTEL_HASWELL_947P-T
JCR1 = CVILU_CF06041H0RB-NH_4P
JCRT1 = CONTE_80431-5K1-152_15P
JDCIN1 = ACES_50312-00541-001_5P-T
JDIMM1 = FOX_AS0A626-U8SN-7F_204P
JDIMM2 = FOX_AS0A626-U4SN-7F_204P
JFAN1 JSPK1 = ACES_85205-04001_4P
JHDD1 = SUYIN_127043FB022G278ZR_22P
JHDMI1 = SUYIN_100042GR019M23DZL_19P-T
JHP1 = SINGA_2SJ2352-000131F_6P
JKB1 = ACES_88514-3001_30P
JKB2 = ACES_88514-2401_24P-T
JLAN1 = SANTA_130456-121_8P
JLED1 = HB_A091020-SAHR21_10P
JLVDS1 = ACES_88341-3001_30P
JODD1 = ALLTO_C18518-11305-L_13P-T
JODD2 = HB_A051020-SAHR21_10P
JP3 = ACES_85205-0400_4P
JPWRB1 JTP1 JUSB3 = ACES_88058-060N_6P
JRTC1 = ACES_50271-0020N-001_2P
JTS1 = ACES_50208-00601-P01_6P
JUSB1 JUSB2 = TAITW_PUBAU1-09FNLSCNN4H0_9P
JWLN1 = BELLW_80003-8041_52P
L30-L32 = CHENG_MBK1608121YZF_2P
L35-L38 L49-L51 L53-L55 L58 L66 L67 = KING_WCM-2012-900T_4P
L44 L45 = L_FBM-11-160808_2P
LA1-LA4 = KC_FBMA-L11-160808-121LMT_2P
LED1 LED2 LED5 LED6 = LED_19-213A-T1D-CP2Q2HY-3T_2P
LH1 = MURAT_BLM18PG181SN1D_L0603_2P
LH2 = MURAT_LQM18FN4R7M00D_2P
LL1 = DELTA_SIA4012-4R7M_2P
LL2 LL3 = KC_FBMA-L11160808601LMA10T_2P
LT1 LT2 = KC_FBMA-L11-201209-221LMA30_2P
LT3 = CYNTE_PG031B-4R7MS_2P
LV1-LV3 LV5 LV6 LV8 LV9 PR914 PR915 R10 R37 R39 R133 R139 R185-R189 R245 R246 R307 R313 R441 R628 R683 R684 R687-R689 RA4 RL7 RV16 RV17 RV43 = R0402_0OHM
LV4 LV7 LV10 PR326 PR421 PR422 R291 R301 R581 = R0603_0OHM
MIC1 = MIC_WM-64PCY_2P
PC522 = C_FP-2R5ME331M-SLR
PC714 = C_MP6VLPS220MC4R2
PC807-PC810 PC951 PC954 PC957 PC960 = C_D2
PC985 = C_MVY25VC220MH10E0-J
PC986 = C_EEEFZ1E101P
PD101 = RB715F_SOT323-3
PD104 PD105 PD201 PD203 = 1N4148WS-7-F_SOD323-2
PD301 PD601 = RB751V-40_SOD323-2
PD302 PD303 = 1SS355_SOD323-2
PF101 PF201 = F_451012MRL
PH201 PH802 PH901 PH902 PR103-PR111 PR201-PR217 PR220 PR225-PR230 PR232 PR233 PR302-PR312 PR314-PR318 PR321 PR322 PR325 PR402 PR403 PR407-PR415 PR502 PR505-PR507 PR509 PR511 PR601 PR602 PR604 PR605 PR607-PR609 PR611-PR613 PR615 PR616 PR618 PR623-PR626 PR701 PR702 PR704-PR707 PR709 PR711 PR712 PR801-PR814 PR816 PR818-PR820 PR827-PR836 PR840-PR851 PR853 PR854 PR856-PR864 PR901-PR907 PR909-PR913 PR916 PR917 PR921-PR923 PR926-PR933 PR935 PR939 PR941 PR942 PR944-PR948 R1 R5-R9 R11 R15 R26-R36 R38 R40 R41 R44-R49 R54 R59 R60 R62-R64 R66-R68 R79 R81 R83 R84 R87-R89 R93-R102 R104-R108 R110 R119 R121-R126 R132 R134-R136 R138 R143 R145 R148 R149 R156-R158 R167-R169 R172 R173 R176-R178 R181-R184 R191-R195 R197 R199 R201-R203 R205 R209 R211 R214-R216 R221-R223 R226-R230 R237 R240 R242 R244 R247-R249 R252 R253 R255 R256 R258-R262 R265-R268 R270-R283 R286-R290 R303 R309 R311 R312 R335 R401-R406 R408 R411 R412 R435 R438 R458 R485 R488 R501 R502 R505-R507 R522 R555 R568 R589 R590 R593-R595 R598 R600 R601 R603-R606 R608 R619 R623 R627 R642 R643 R646 R647 R649 R650 R652 R653 R669 R675 R694 R695 R701 R710 R716 R722 R740 R764 R765 R778 R780 R781 R868 R869 R5581 R5583 RA1 RA2 RA5-RA9 RA12-RA23 RA492 RC1 RL3 RL4 RL6 RL8-RL12 RT4 RT8-RT10 RT12 RV1-RV6 RV11-RV14 RV18-RV35 RV37 RV38 RV41 RV42 RV44 RV47-RV91 = R_0402
PJ2 PJ3 PJ202 PJ503 = JUMP_43X39
PL101 PL102 PL801 PL901 = L_1812-1806
PL201 = CHENG_SMB3025500YA_2P
PL301 = CYNTE_PCMB063T-100MS_2P
PL302 = KARSO_KJ1040-3R3M_2P
PL401 PL403 PL502 PL603 PL606 PL702 = TAI-T_HCB2012KF-121T50_2P
PL402 PL404 = TAI-T_VMPI0703AR-100M-Z01_2P
PL501 = CYNTE_PCMB104T-1R0MH_2P
PL601 PL605 PL701 = CYNTE_PCMB063T-1R0MS_2P
PL604 = CYNTE_PHT32251B-1R0MS_2P
PL802 PL803 = CYNTE_PDME064T-R36MS1R405_4P
PL902-PL904 = TAI-T_VMPI1004AR-R36M-Z03_4P
PQ101 PQ102 PQ202 PQ307 = 2N7002DW-7-F_SOT363-6
PQ201 = SSM3K7002FU_SC70-3
PQ205-PQ209 PQ308 PQ313 PQ314 = 2N7002W-T-R7_SOT323-3
PQ301 PQ302 PQ312 = AO4407A_SO8
PQ303 PQ305 PQ311 = DTC115EUA_SC70-3
PQ304 = DTA144EUA_SC70-3
PQ306 = 2N7002KW_SOT323-3
PQ309 PQ310 PQ701 PQ702 = AO4466L_SO8
PQ501 = TPCA8065-H_PPAK56-8-5
PQ502 = TPCA8059-H_PPAK56-8-5
PQ801 PQ802 = CSD87351Q5D_SON8-7
PQ901 PQ903 PQ905 = MDU1516URH_POWERDFN56-8-5
PQ902 PQ904 PQ906 = MDU1511RH_POWERDFN56-8-5
PR101 PR102 PR320 PR501 PR514 PR713 PR817 PR852 PR908 PR918-PR920 PR924 PR925 PR936 R78 R304 R644 R645 R655 R659 R777 RV36 RV39 = R_0603
PR301 PR324 = R_1206_4P-D
PR319 PR323 PR404 PR406 PR515 PR603 PR610 PR614 PR714 PR826 PR855 PR937 PR940 PR943 = R_1206
PU101 PU201 = LM393DG_SO8
PU202 = G9191-330T1U_SOT23-5
PU301 = BQ24737RGRR_VQFN20_3P5X3P5
PU401 = SY8208BQNC_QFN10_3X3
PU402 = SY8208CQNC_QFN10_3X3
PU501 = RT8207MZQW_WQFN20_3X3
PU601 PU604 = SY8208DQNC_QFN10_3X3
PU603 = SY8032ABC_SOT23-6
PU701 = TPS51219RTER_QFN16_3X3
PU801 = ISL62883CHRTZ-T_TQFN40_5X5
PU901 = NCP81103MNTWG_QFN36_5X5
PU902 = NCP81151MNTBG_DFN8_2X2
Q1 Q37 Q93 Q95 = 2N7002H_SOT23-3
Q6 Q100 Q117 Q124 = DTC124EKAT146_SC59-3
Q11 Q63 Q130 QV3 = 2N7002DW-T-R7_SOT363-6
Q83 Q99 Q156 QL1 = PMV65XP_SOT23-3
